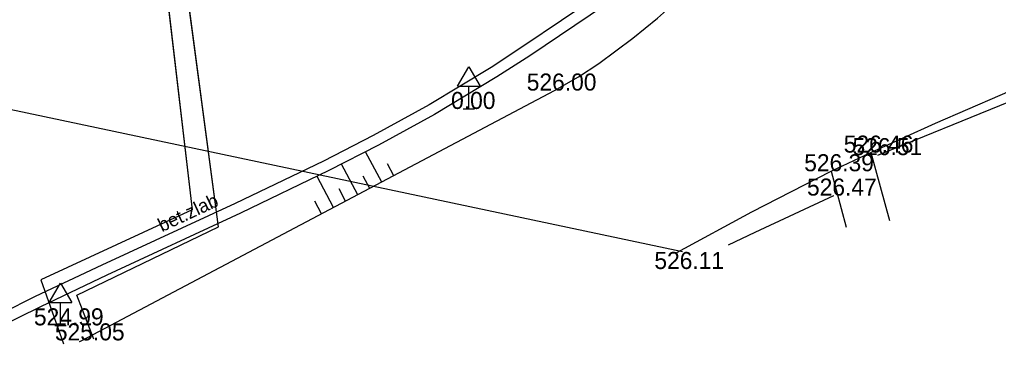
# Model space of a CAD drawing. Extents: x -669393 to -668650, y -1126925 to -1126294.
# Drawn here: x -669021.36 to -668978.28, y -1126912.06 to -1126896.89 of the extents above; entities that cross this region are included whole.
import ezdxf

# ---------------------------------------------------------------- set-up
doc = ezdxf.new("R2010")
doc.units = 0
for name, color, linetype in [('G_Bod_tecka', 7, 'Continuous'), ('G_Bod_vyska', 7, 'Continuous'), ('G_Breh_Teren', 7, 'Continuous'), ('G_Objekty_dopravni', 7, 'Continuous'), ('G_Plochy_zpevnene', 7, 'Continuous'), ('G_Popisy_povrchu', 7, 'Continuous'), ('G_Vyskove_srafy', 7, 'Continuous'), ('G_Z_ELsilove_nadz_kotovane', 7, 'Continuous'), ('G_Z_ELsilove_podz_kotovane', 7, 'Continuous'), ('G_Zabradli_Svodidla', 7, 'Continuous'), ('Vrstva 17', 7, 'Continuous')]:
    doc.layers.add(name, color=color, linetype=linetype)

msp = doc.modelspace()

# ---------------------------------------------------------------- linework, layer by layer
at = {"layer": 'G_Bod_tecka'}
for p, q in [((-668997.82, -1126900.01), (-668997.82, -1126900.01)), ((-669001.59, -1126900.82), (-669001.59, -1126900.82)), ((-668983.9, -1126902.74), (-668983.9, -1126902.74)), ((-668983.59, -1126902.85), (-668983.59, -1126902.85)), ((-668985.65, -1126903.56), (-668985.65, -1126903.56)), ((-668985.53, -1126904.63), (-668985.53, -1126904.63)), ((-669019.56, -1126910.34), (-669019.56, -1126910.34)), ((-669018.62, -1126911), (-669018.62, -1126911))]:
    msp.add_line(p, q, dxfattribs=at)
at = {"layer": 'G_Breh_Teren'}
msp.add_lwpolyline([(-669018.725, -1126911.048), (-669018.62, -1126911)], dxfattribs=at)
at = {"layer": 'G_Objekty_dopravni'}
for points in [[(-669002.09, -1126899.82), (-669001.59, -1126898.97)], [(-669001.59, -1126898.97), (-669001.09, -1126899.82)], [(-669002.09, -1126899.82), (-669001.09, -1126899.82)], [(-669001.59, -1126900.82), (-669001.59, -1126899.82)], [(-669001.84, -1126900.82), (-669001.34, -1126900.82)], [(-669020.06, -1126909.34), (-669019.56, -1126908.49)], [(-669019.56, -1126908.49), (-669019.06, -1126909.34)], [(-669020.06, -1126909.34), (-669019.06, -1126909.34)], [(-669019.56, -1126910.34), (-669019.56, -1126909.34)], [(-669019.81, -1126910.34), (-669019.31, -1126910.34)]]:
    msp.add_lwpolyline(points, dxfattribs=at)
at = {"layer": 'G_Plochy_zpevnene'}
msp.add_line((-668985.65, -1126903.56), (-668983.9, -1126902.74), dxfattribs=at)
for points in [[(-668991.93, -1126893.76), (-668994.94, -1126895.8), (-668998.91, -1126898.48), (-669000.35, -1126899.41), (-669003.1, -1126901.06), (-669005.56, -1126902.41), (-669007.75, -1126903.53), (-669011.64, -1126905.4), (-669017.52, -1126908.13), (-669020.44, -1126909.52), (-669023.34, -1126910.95), (-669025.5, -1126912.058)], [(-668995.87, -1126898.82), (-668994.37, -1126897.71), (-668993.28, -1126896.82), (-668990.12, -1126894)], [(-668995.86, -1126895.8), (-668999.17, -1126898.04), (-669000.6, -1126898.99), (-669003.34, -1126900.64), (-669005.8, -1126901.99), (-669007.98, -1126903.11), (-669011.87, -1126904.98), (-669017.74, -1126907.69), (-669020.67, -1126909.07), (-669023.6, -1126910.53)], [(-669018.705, -1126911.045), (-669018.62, -1126911), (-669008.22, -1126905.51), (-668997.82, -1126900.01), (-668996.76, -1126899.4), (-668995.87, -1126898.82)], [(-668983.9, -1126902.74), (-668981.06, -1126901.45), (-668976.78, -1126899.59)], [(-668983.9, -1126902.74), (-668983.072, -1126905.733)], [(-668992.439, -1126907.129), (-668989.13, -1126905.35), (-668985.65, -1126903.56)], [(-668985.65, -1126903.56), (-668984.99, -1126906.019)]]:
    msp.add_lwpolyline(points, dxfattribs=at)
at = {"layer": 'G_Vyskove_srafy'}
for points in [[(-669005.42, -1126904.04), (-669006.13, -1126902.7)], [(-669006.48, -1126904.6), (-669007.2, -1126903.25)], [(-669004.89, -1126903.76), (-669005.17, -1126903.23)], [(-669007.54, -1126905.16), (-669008.27, -1126903.79)], [(-669005.95, -1126904.32), (-669006.24, -1126903.78)], [(-669007.02, -1126904.88), (-669007.3, -1126904.34)], [(-669008.08, -1126905.44), (-669008.37, -1126904.88)]]:
    msp.add_lwpolyline(points, dxfattribs=at)
at = {"layer": 'G_Z_ELsilove_nadz_kotovane'}
msp.add_lwpolyline([(-669147.386, -1126902.4), (-669107.692, -1126901.025), (-669049.469, -1126898.989), (-669046.24, -1126898.876), (-669033.175, -1126898.419), (-668992.185, -1126907.092)], dxfattribs=at)
at = {"layer": 'G_Z_ELsilove_podz_kotovane'}
for points in [[(-669017.66, -1126872.32), (-669017.53, -1126873.04), (-669013.77, -1126905.26), (-669020.43, -1126908.34), (-669019.424, -1126911.152)], [(-669018.093, -1126910.954), (-669018.84, -1126909.01), (-669012.61, -1126906.01), (-669017.05, -1126872.56), (-669017.66, -1126872.32)]]:
    msp.add_lwpolyline(points, dxfattribs=at)
at = {"layer": 'G_Zabradli_Svodidla'}
for points in [[(-668983.59, -1126902.85), (-668977.82, -1126900.5), (-668972.06, -1126898.15), (-668971.28, -1126897.88), (-668970.57, -1126897.7), (-668969.31, -1126897.5), (-668967.38, -1126897.37), (-668965.46, -1126897.29), (-668964.29, -1126897.19), (-668963.41, -1126897.15), (-668962.75, -1126897.19), (-668962.26, -1126897.28), (-668961.89, -1126897.38), (-668961.33, -1126897.63), (-668960.78, -1126898), (-668960.58, -1126898.21), (-668960.44, -1126898.57), (-668960.39, -1126898.95), (-668960.35, -1126899.49), (-668960.39, -1126899.76), (-668960.48, -1126900.02), (-668960.94, -1126900.88), (-668961.83, -1126902.29), (-668962.059, -1126902.601)], [(-668990.166, -1126906.791), (-668988.99, -1126906.24), (-668985.53, -1126904.63)]]:
    msp.add_lwpolyline(points, dxfattribs=at)
at = {"layer": 'Vrstva 17'}
for p, q in [((-669012.61, -1126906.01), (-669017.05, -1126872.56)), ((-669017.53, -1126873.04), (-669013.77, -1126905.26)), ((-669013.77, -1126905.26), (-669020.43, -1126908.34)), ((-669018.84, -1126909.01), (-669012.61, -1126906.01)), ((-669020.43, -1126908.34), (-669019.424, -1126911.152)), ((-669018.093, -1126910.954), (-669018.84, -1126909.01))]:
    msp.add_line(p, q, dxfattribs=at)

# ---------------------------------------------------------------- texts
at = {"layer": 'G_Bod_vyska'}
for s, p in [('526.00', (-668999.041, -1126900.01)), ('0.00', (-669002.37, -1126900.82)), ('526.46', (-668985.092, -1126902.74)), ('526.51', (-668984.706, -1126902.85)), ('526.39', (-668986.83, -1126903.56)), ('526.47', (-668986.708, -1126904.63)), ('526.11', (-668993.424, -1126907.86)), ('524.99', (-669020.728, -1126910.34)), ('525.05', (-669019.806, -1126911))]:
    msp.add_text(s, height=0.75, dxfattribs=at).set_placement(p)
at = {"layer": 'G_Popisy_povrchu'}
msp.add_text('bet.zlab', height=0.6, rotation=24.9651, dxfattribs=at).set_placement((-669015.096, -1126906.245))

doc.saveas('drawing.dxf')
